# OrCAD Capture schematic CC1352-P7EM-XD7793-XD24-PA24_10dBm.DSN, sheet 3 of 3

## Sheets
3 Revision
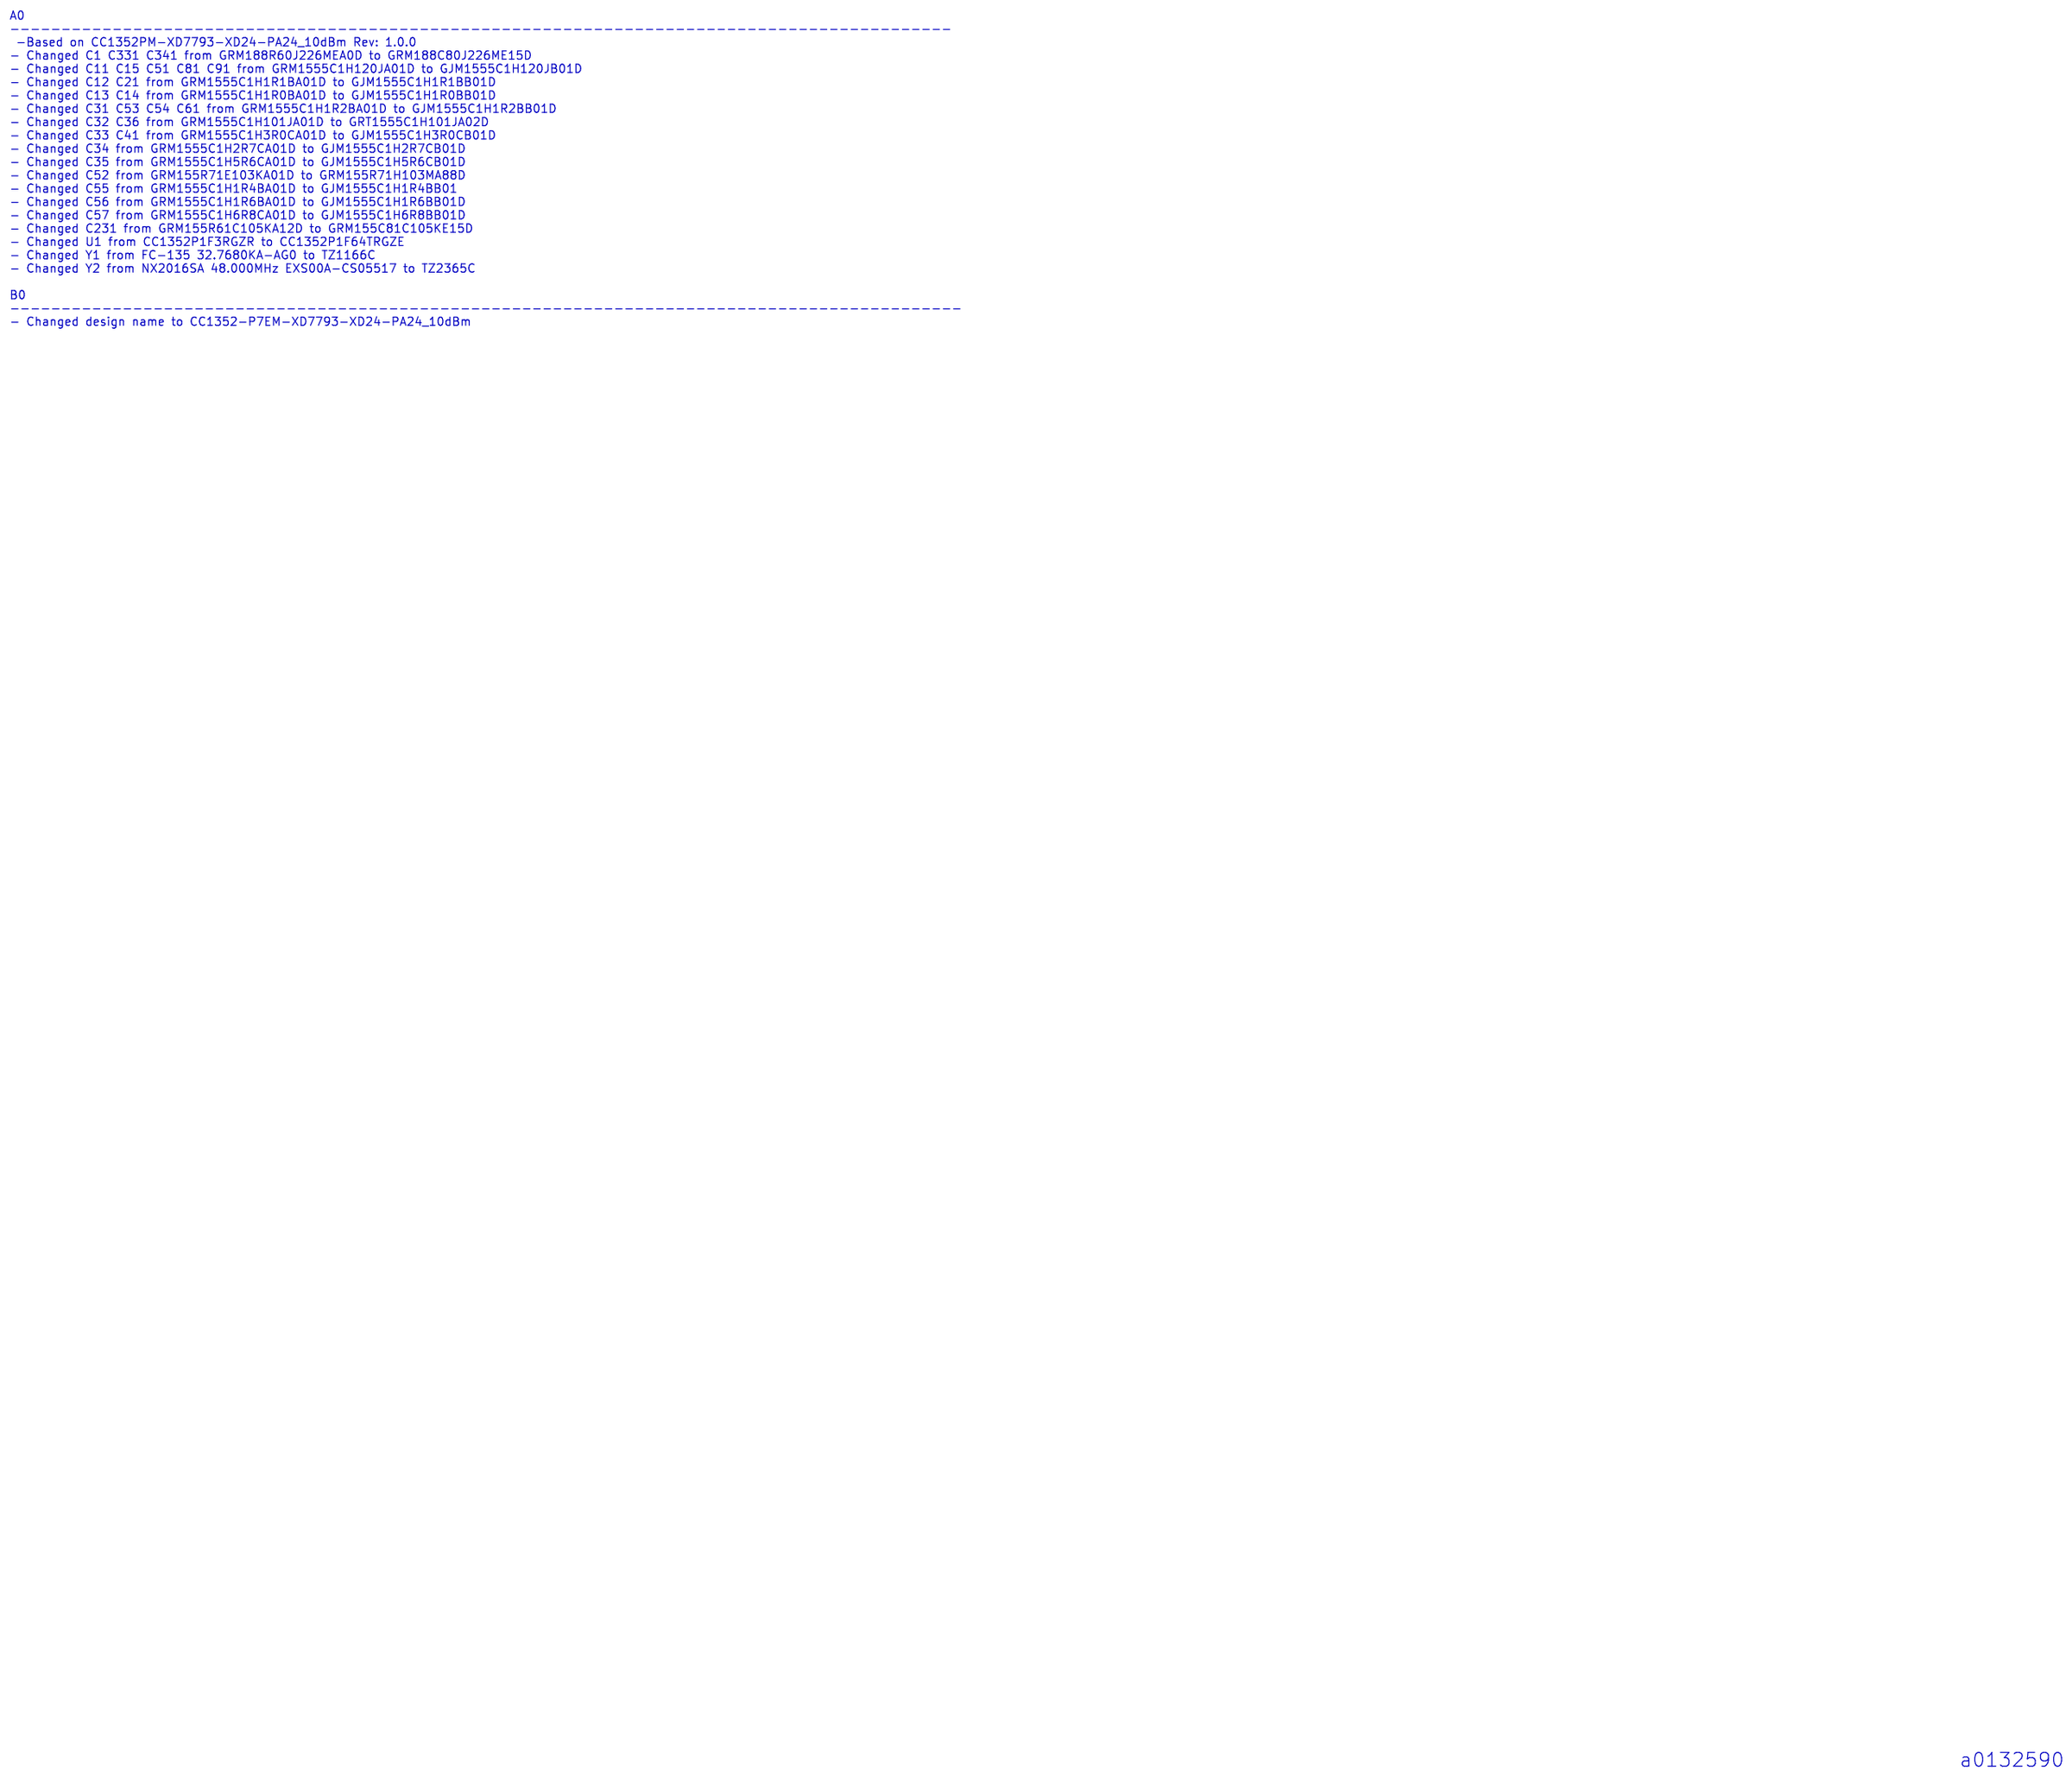
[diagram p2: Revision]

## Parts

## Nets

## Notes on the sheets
sheet 3
- A0
  --------------------------------------------------------------------------------------------
   -Based on CC1352PM-XD7793-XD24-PA24_10dBm Rev: 1.0.0
  - Changed C1 C331 C341 from GRM188R60J226MEA0D to GRM188C80J226ME15D
  - Changed C11 C15 C51 C81 C91 from GRM1555C1H120JA01D to GJM1555C1H120JB01D
  - Changed C12 C21 from GRM1555C1H1R1BA01D to GJM1555C1H1R1BB01D
  - Changed C13 C14 from GRM1555C1H1R0BA01D to GJM1555C1H1R0BB01D
  - Changed C31 C53 C54 C61 from GRM1555C1H1R2BA01D to GJM1555C1H1R2BB01D
  - Changed C32 C36 from GRM1555C1H101JA01D to GRT1555C1H101JA02D
  - Changed C33 C41 from GRM1555C1H3R0CA01D to GJM1555C1H3R0CB01D
  - Changed C34 from GRM1555C1H2R7CA01D to GJM1555C1H2R7CB01D
  - Changed C35 from GRM1555C1H5R6CA01D to GJM1555C1H5R6CB01D
  - Changed C52 from GRM155R71E103KA01D to GRM155R71H103MA88D
  - Changed C55 from GRM1555C1H1R4BA01D to GJM1555C1H1R4BB01
  - Changed C56 from GRM1555C1H1R6BA01D to GJM1555C1H1R6BB01D
  - Changed C57 from GRM1555C1H6R8CA01D to GJM1555C1H6R8BB01D
  - Changed C231 from GRM155R61C105KA12D to GRM155C81C105KE15D
  - Changed U1 from CC1352P1F3RGZR to CC1352P1F64TRGZE
  - Changed Y1 from FC-135 32.7680KA-AG0 to TZ1166C
  - Changed Y2 from NX2016SA 48.000MHz EXS00A-CS05517 to TZ2365C
  B0
  ---------------------------------------------------------------------------------------------
  - Changed design name to CC1352-P7EM-XD7793-XD24-PA24_10dBm
- a0132590
